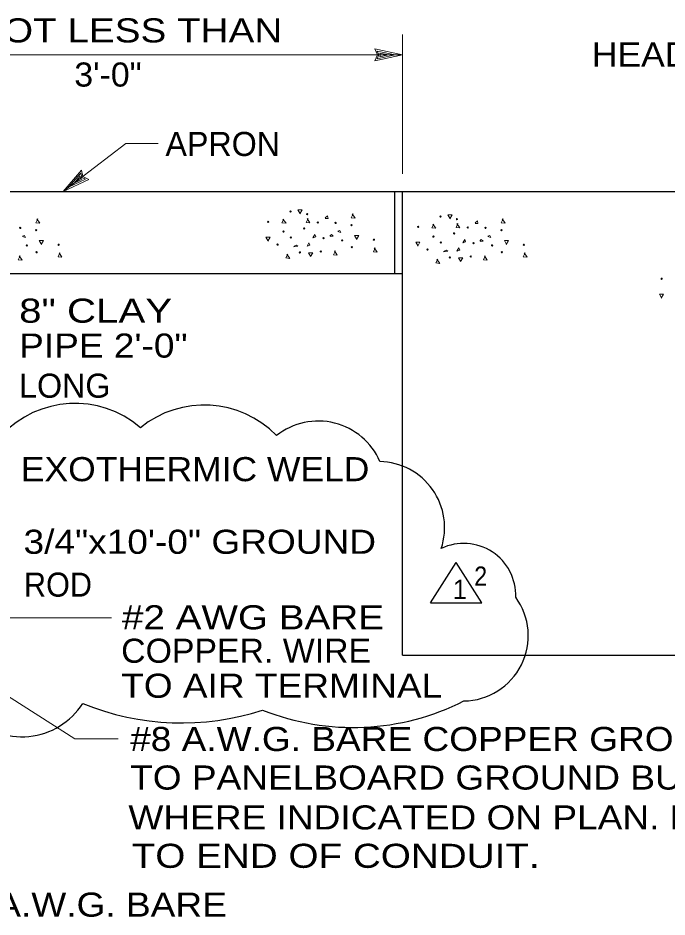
# Model space of a CAD drawing. Extents: x -39.6 to 16.1, y -17.6 to 34.
# Drawn here: x -8.378 to -5.01, y -3.13 to 1.533 of the extents above; entities that cross this region are included whole.
import ezdxf
from ezdxf.enums import TextEntityAlignment as Align

# ---------------------------------------------------------------- set-up
doc = ezdxf.new("R2010")
doc.units = 0
doc.header["$LTSCALE"] = 0.05
doc.layers.add('1', color=7, linetype='Continuous', lineweight=13)
doc.layers.add('2', color=7, linetype='Continuous', lineweight=13)

msp = doc.modelspace()

# ---------------------------------------------------------------- linework, layer by layer
at = {"layer": '1'}
for p, q in [((-6.38321, 0.72442), (-6.38321, 1.44742)), ((-6.38321, 1.34142), (-6.52721, 1.37242)), ((-6.42021, 1.34142), (-6.51421, 1.36142)), ((-6.50521, 1.34142), (-6.51421, 1.36142)), ((-9.38021, 1.34142), (-6.38321, 1.34142)), ((-6.38321, 1.34142), (-6.52721, 1.31042)), ((-6.42021, 1.34142), (-6.51421, 1.32142)), ((-6.51421, 1.32142), (-6.50521, 1.34142)), ((-6.45621, 1.34142), (-6.50121, 1.35042)), ((-6.49721, 1.34142), (-6.50121, 1.35042)), ((-6.45621, 1.34142), (-6.50121, 1.33142)), ((-6.50121, 1.33142), (-6.49721, 1.34142)), ((-7.81921, 0.88142), (-7.65121, 0.88142)), ((-8.11521, 0.65542), (-8.05221, 0.72842)), ((-8.08621, 0.67642), (-8.05621, 0.71242)), ((-8.05621, 0.71242), (-8.05421, 0.70142)), ((-8.05421, 0.70142), (-8.04521, 0.69742)), ((-8.05221, 0.72842), (-8.04721, 0.70642)), ((-8.04721, 0.70642), (-8.02821, 0.69642)), ((-8.14421, 0.63242), (-8.01121, 0.69542)), ((-8.11521, 0.65542), (-8.02821, 0.69642)), ((-8.08621, 0.67642), (-8.04521, 0.69742)), ((-8.73822, -1.57821), (-7.89371, -1.57821)), ((-8.08377, -2.20527), (-7.85877, -2.20527))]:
    msp.add_line(p, q, dxfattribs=at)
at = {"layer": '1', "lineweight": 25}
for p, q in [((-10.28021, 0.63242), (-3.87821, 0.63242)), ((-6.42221, 0.20742), (-6.42221, 0.63242)), ((-6.38321, -1.77158), (-6.38321, 0.63342)), ((-8.98221, 0.20742), (-6.38321, 0.20742)), ((-6.23761, -1.49985), (-6.10461, -1.29085)), ((-5.97161, -1.49985), (-6.10461, -1.29085)), ((-6.23761, -1.49985), (-5.97161, -1.49985)), ((-6.38321, -1.77158), (-2.44621, -1.77158))]:
    msp.add_line(p, q, dxfattribs=at)
at = {"layer": '1'}
for points in [[(-6.52721, 1.31042), (-6.51321, 1.34142), (-6.52721, 1.37242)], [(-7.81921, 0.88142), (-8.14421, 0.63242), (-8.04921, 0.74442)], [(-8.04921, 0.74442), (-8.04121, 0.71142), (-8.01121, 0.69542)], [(-8.08377, -2.20527), (-9.20121, -1.49358), (-9.06321, -1.54458)]]:
    msp.add_lwpolyline(points, dxfattribs=at)
at = {"layer": '1', "lineweight": 25}
for centre, radius, start, end in [((-8.08232, -0.98618), 0.52021, 49.25934, 137.21745), ((-7.41189, -1.00078), 0.52592, 44.39557, 128.9941), ((-6.81988, -0.90556), 0.34803, 23.36912, 128.40955), ((-6.50777, -1.11085), 0.34341, 341.69586, 88.77008), ((-6.06523, -1.46248), 0.27019, 358.01201, 115.54156), ((-6.06913, -1.67091), 0.33862, 270.84231, 36.0042), ((-8.3569, -1.82236), 0.37288, 223.40398, 327.48388), ((-7.52894, -0.75997), 1.36324, 247.87089, 287.95536), ((-6.63877, -0.87775), 1.26926, 248.27039, 296.91812)]:
    msp.add_arc(centre, radius, start, end, dxfattribs=at)
at = {"layer": '2'}
for p, q in [((-6.78421, 0.49642), (-6.77221, 0.50642)), ((-6.00621, 0.47042), (-5.99421, 0.48042))]:
    msp.add_line(p, q, dxfattribs=at)
for points in [[(-6.91521, 0.52142), (-6.92521, 0.53842), (-6.90321, 0.53842), (-6.91521, 0.51742)], [(-6.63921, 0.51742), (-6.64921, 0.49742), (-6.62821, 0.49542), (-6.64421, 0.51742)], [(-8.27521, 0.49142), (-8.28521, 0.47142), (-8.26421, 0.46942), (-8.28021, 0.49142)], [(-6.99821, 0.49042), (-7.00821, 0.47042), (-6.98721, 0.46842), (-7.00321, 0.49042)], [(-6.87321, 0.49242), (-6.88321, 0.47242), (-6.86321, 0.47042), (-6.87821, 0.49242)], [(-6.77221, 0.50742), (-6.76921, 0.49242), (-6.78421, 0.49242)], [(-6.13721, 0.49542), (-6.14721, 0.51242), (-6.12521, 0.51242), (-6.13721, 0.49142)], [(-6.09521, 0.46642), (-6.10521, 0.44642), (-6.08521, 0.44442), (-6.10021, 0.46642)], [(-5.99421, 0.48142), (-5.99121, 0.46642), (-6.00621, 0.46642)], [(-5.86121, 0.49142), (-5.87121, 0.47142), (-5.85021, 0.46942), (-5.86621, 0.49142)], [(-6.71821, 0.42742), (-6.70821, 0.43042), (-6.70321, 0.42042), (-6.71821, 0.42542)], [(-6.22021, 0.46442), (-6.23021, 0.44442), (-6.20921, 0.44242), (-6.22521, 0.46442)], [(-8.35421, 0.40142), (-8.34421, 0.40442), (-8.33921, 0.39442), (-8.35421, 0.39942)], [(-8.25821, 0.36142), (-8.26821, 0.37842), (-8.24621, 0.37842), (-8.25821, 0.35842)], [(-7.08221, 0.37942), (-7.09221, 0.39642), (-7.07021, 0.39642), (-7.08221, 0.37542)], [(-6.75921, 0.40142), (-6.75221, 0.40942), (-6.74321, 0.40142), (-6.75721, 0.39942)], [(-6.62221, 0.38742), (-6.63221, 0.40442), (-6.61021, 0.40442), (-6.62221, 0.38442)], [(-5.98121, 0.37542), (-5.97421, 0.38342), (-5.96521, 0.37542), (-5.97921, 0.37342)], [(-5.94021, 0.40142), (-5.93021, 0.40442), (-5.92521, 0.39442), (-5.94021, 0.39942)], [(-5.84421, 0.36142), (-5.85421, 0.37842), (-5.83221, 0.37842), (-5.84421, 0.35842)], [(-6.94421, 0.34942), (-6.93421, 0.35542), (-6.92521, 0.34942), (-6.94921, 0.34542)], [(-6.52421, 0.34042), (-6.53421, 0.32042), (-6.51421, 0.31842), (-6.52921, 0.34042)], [(-6.30421, 0.35342), (-6.31421, 0.37042), (-6.29221, 0.37042), (-6.30421, 0.34942)], [(-6.16621, 0.32342), (-6.15621, 0.32942), (-6.14721, 0.32342), (-6.17121, 0.31942)], [(-8.36721, 0.29942), (-8.37721, 0.27942), (-8.35721, 0.27742), (-8.37221, 0.29942)], [(-8.16021, 0.31442), (-8.17021, 0.29442), (-8.15021, 0.29242), (-8.16521, 0.31442)], [(-6.97821, 0.30842), (-6.98821, 0.28842), (-6.96721, 0.28642), (-6.98321, 0.30842)], [(-6.86021, 0.29842), (-6.87021, 0.31542), (-6.84821, 0.31542), (-6.86021, 0.29542)], [(-6.73121, 0.32542), (-6.74121, 0.30542), (-6.72121, 0.30342), (-6.73621, 0.32542)], [(-6.20021, 0.28242), (-6.21021, 0.26242), (-6.18921, 0.26042), (-6.20521, 0.28242)], [(-6.08221, 0.27242), (-6.09221, 0.28942), (-6.07021, 0.28942), (-6.08221, 0.26942)], [(-5.95321, 0.29942), (-5.96321, 0.27942), (-5.94321, 0.27742), (-5.95821, 0.29942)], [(-5.74621, 0.31442), (-5.75621, 0.29442), (-5.73621, 0.29242), (-5.75121, 0.31442)], [(-5.04021, 0.08442), (-5.05021, 0.10142), (-5.02821, 0.10142), (-5.04021, 0.08042)]]:
    msp.add_lwpolyline(points, dxfattribs=at)
for points in [[(-6.84821, 0.39242), (-6.83821, 0.40942), (-6.83321, 0.39742)], [(-6.07021, 0.36642), (-6.06021, 0.38342), (-6.05521, 0.37142)], [(-6.87821, 0.34942), (-6.86821, 0.36642), (-6.86321, 0.35442)], [(-6.10021, 0.32342), (-6.09021, 0.34042), (-6.08521, 0.32842)]]:
    msp.add_lwpolyline(points, close=True, dxfattribs=at)
for centre in [(-6.96371, 0.52917), (-6.87821, 0.51567), (-7.08021, 0.47567), (-6.82271, 0.47217), (-6.73021, 0.47017), (-6.18571, 0.50317), (-6.10021, 0.48967), (-8.36621, 0.44417), (-8.28371, 0.43267), (-7.00071, 0.42517), (-6.89321, 0.44167), (-6.64771, 0.45867), (-6.30221, 0.44967), (-6.04471, 0.44617), (-5.95221, 0.44417), (-5.86971, 0.43267), (-6.96221, 0.39467), (-6.79221, 0.39117), (-6.69621, 0.37967), (-6.53121, 0.38317), (-6.22271, 0.39917), (-6.11521, 0.41567), (-8.33221, 0.35367), (-8.16721, 0.35717), (-7.03121, 0.35767), (-6.64571, 0.34417), (-6.25321, 0.33167), (-6.18421, 0.36867), (-6.01421, 0.36517), (-5.91821, 0.35367), (-5.75321, 0.35717), (-8.28171, 0.31817), (-6.91521, 0.31717), (-6.80721, 0.32217), (-6.13721, 0.29117), (-6.02921, 0.29617), (-5.86771, 0.31817), (-5.03821, 0.18067)]:
    msp.add_circle(centre, 0.00325, dxfattribs=at)

# ---------------------------------------------------------------- texts
at = {"layer": '1'}
for s, height, width, p in [('NOT LESS THAN', 0.125, 1.2, (-7.80371, 1.40642)), ('3\'-0"', 0.125, 1.05, (-7.91121, 1.17742)), ('2', 0.1, 0.9, (-5.97733, -1.41211))]:
    msp.add_text(s, height=height, dxfattribs=dict(at, width=width)).set_placement(p, align=Align.CENTER)
for s, width, p in [('HEAD WALL', 1.1, (-5.40021, 1.28142)), ('8" CLAY', 1.25, (-8.37221, -0.04758)), ('PIPE 2\'-0"', 1.15, (-8.37221, -0.22858)), ('EXOTHERMIC WELD', 1.1, (-8.36314, -0.86958)), ('3/4"x10\'-0" GROUND', 1.15, (-8.34931, -1.2463)), ('ROD', 0.95, (-8.3471, -1.4686)), ('#2 AWG BARE', 1.2, (-7.83878, -1.63804)), ('COPPER. WIRE', 1.05, (-7.84281, -1.81152)), ('TO AIR TERMINAL', 1.15, (-7.84281, -1.99306)), ('#8 A.W.G. BARE COPPER GROUND CONDUCTOR', 1.15, (-7.7962, -2.26928)), ('TO PANELBOARD GROUND BUS OR SURGE ARRESTER', 1.15, (-7.7962, -2.46928)), ('WHERE INDICATED ON PLAN. BOND GROUND CONDUCTOR', 1.15, (-7.8052, -2.67628)), ('TO END OF CONDUIT.', 1.2, (-7.7882, -2.87528)), ('#1/0 A.W.G. BARE', 1.15, (-8.91821, -3.12858))]:
    msp.add_text(s, height=0.125, dxfattribs=dict(at, width=width)).set_placement(p)
for s, height, p in [('APRON', 0.125, (-7.31571, 0.81742)), ('1', 0.1, (-6.0853, -1.48085))]:
    msp.add_text(s, height=height, dxfattribs=at).set_placement(p, align=Align.CENTER)
msp.add_text('LONG', height=0.125, dxfattribs=at).set_placement((-8.37221, -0.43658))

doc.saveas('drawing.dxf')
